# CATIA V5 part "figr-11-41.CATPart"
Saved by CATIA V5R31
Part number: Part1
Bounding box of the stored display mesh (mm): x -59 to 59, y -60 to 60, z 0 to 39.8
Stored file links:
  D:\PROJECTS\Project 2021\US EDITION\CATIA V5 6R 2021\Resources\Part Files\c11_catia_v5_6r2021_prt\figr-11-41.CATPart
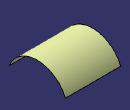
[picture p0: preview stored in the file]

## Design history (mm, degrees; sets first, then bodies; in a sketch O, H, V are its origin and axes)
Set1
  Extrude1: Element1 Sketch1, Lim1 59, Lim2 59, Direction yz-plane
Body1 (main body)
  Sketch1 on yz-plane, origin (0, 0, 0), H (0, 1, 0), V (0, 0, 1)
    arc A1 centre (0, -25) radius 65 from (-60, 0) to (60, 0) cw
    point P2 (-60, 0)
    point P3 (60, 0)
    coincidence: P2 H, P3 H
